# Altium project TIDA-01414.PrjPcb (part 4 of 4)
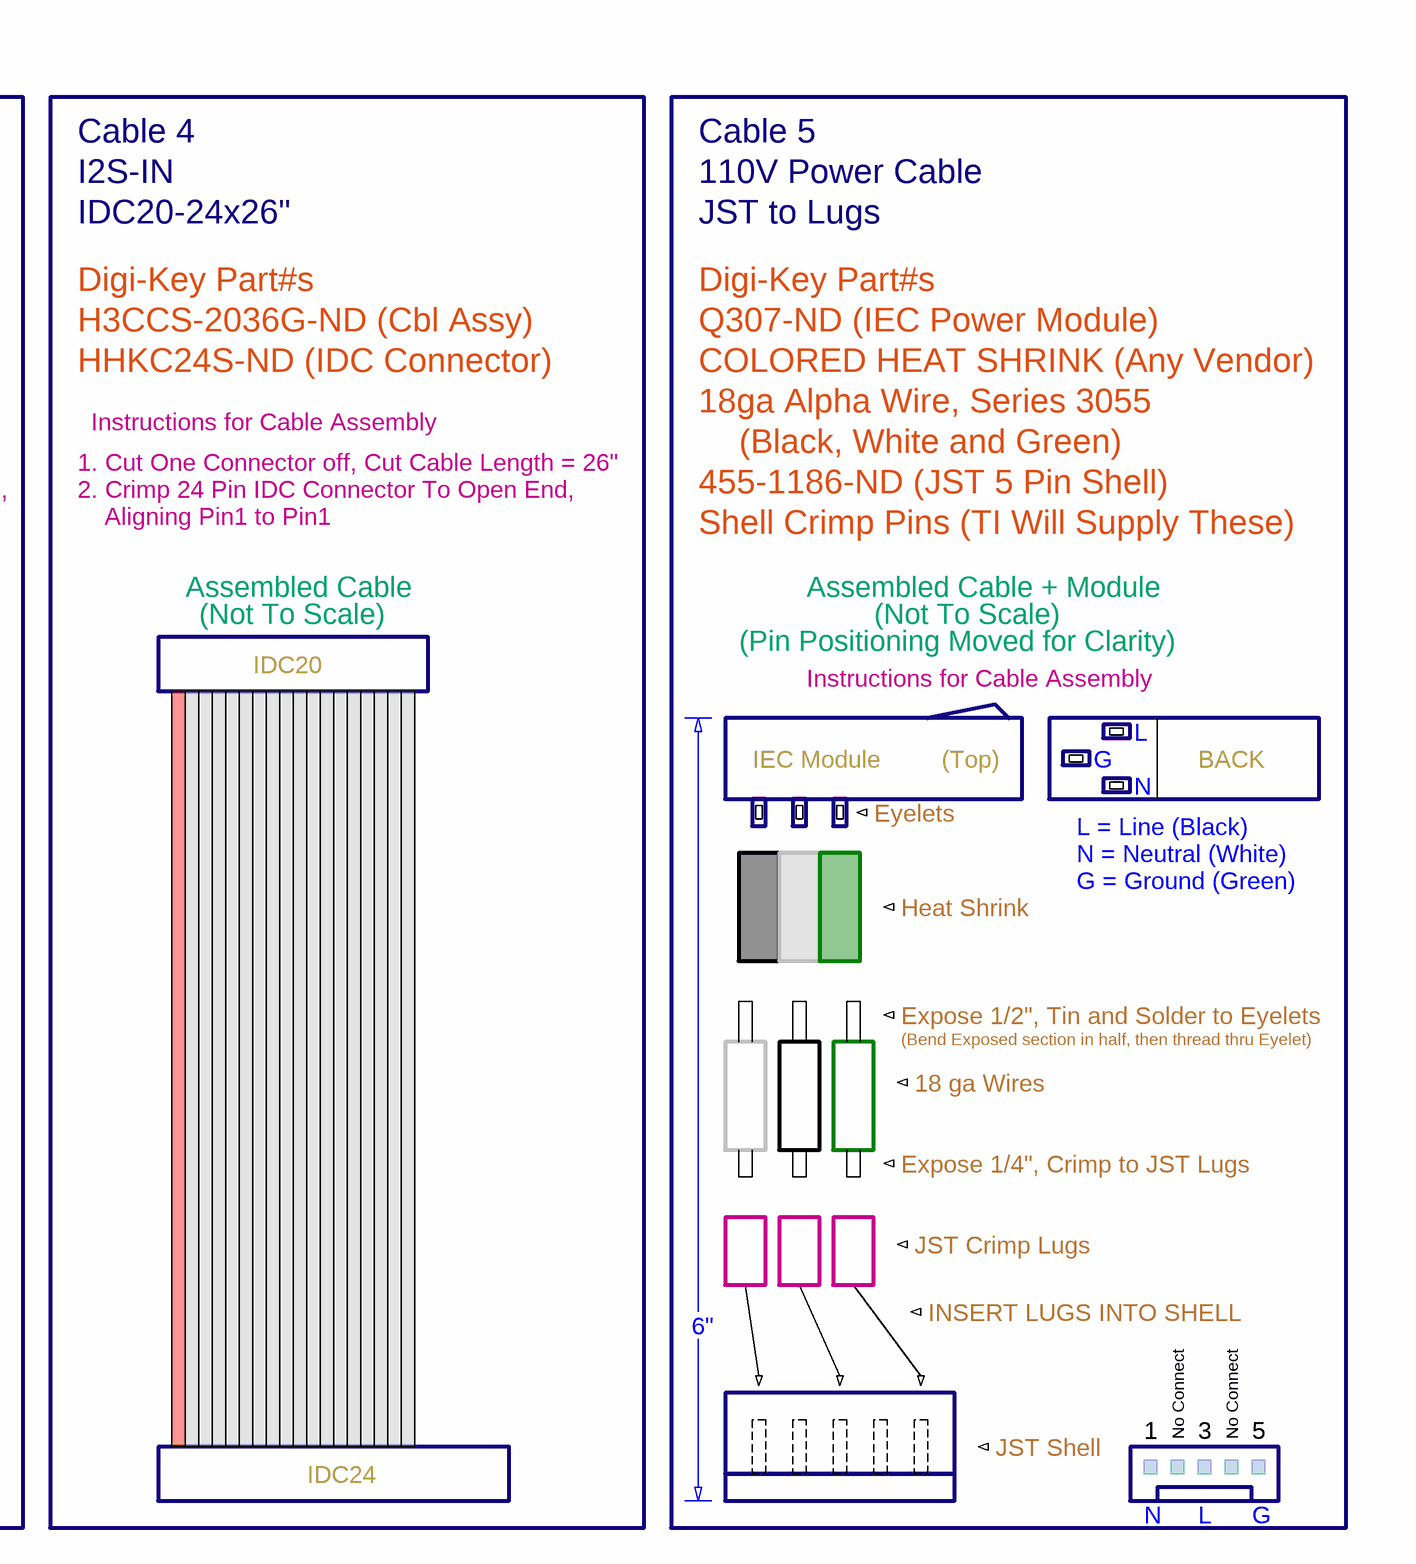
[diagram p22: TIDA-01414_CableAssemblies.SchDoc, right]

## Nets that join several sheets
3.3V: TIDA-01414_Control (30 pins), TIDA-01414_SurroundChannel (J2.6 J2.8), TIDA-01414_SubWooferChannel (11 pins), TIDA-01414_PowerSupplies (J1.1 J8.1)
3.3V-2: TIDA-01414_FrontLeftChannel (11 pins), TIDA-01414_CenterChannel (11 pins), TIDA-01414_PowerSupplies (C24.1 D15.1 VR5.4)
3.3V-3: TIDA-01414_Control (21 pins), TIDA-01414_ClockDrivers (20 pins), TIDA-01414_PowerSupplies (J1.2)
3.3V-4: TIDA-01414_SurroundChannel (15 pins), TIDA-01414_UpChannel (11 pins), TIDA-01414_FrontRightChannel (11 pins), TIDA-01414_PowerSupplies (J6.2)
12V: TIDA-01414_ClockDrivers (R18.1 R26.1), TIDA-01414_SurroundChannel (5 pins), TIDA-01414_UpChannel (5 pins), TIDA-01414_FrontRightChannel (5 pins), TIDA-01414_FrontLeftChannel (5 pins), TIDA-01414_CenterChannel (5 pins), TIDA-01414_SubWooferChannel (L600.1), TIDA-01414_PowerSupplies (J4.1 R49.1)
12V-DC: TIDA-01414_SurroundChannel (J2.2 J2.4), TIDA-01414_PowerSupplies (J5.2)
GND: TIDA-01414_Control (62 pins), TIDA-01414_ClockDrivers (42 pins), TIDA-01414_SurroundChannel (84 pins), TIDA-01414_UpChannel (52 pins), TIDA-01414_FrontRightChannel (52 pins), TIDA-01414_FrontLeftChannel (52 pins), TIDA-01414_CenterChannel (52 pins), TIDA-01414_SubWooferChannel (30 pins), TIDA-01414_PowerSupplies (38 pins)
PVDD: TIDA-01414_SurroundChannel (12 pins), TIDA-01414_UpChannel (12 pins), TIDA-01414_FrontRightChannel (12 pins), TIDA-01414_FrontLeftChannel (12 pins), TIDA-01414_CenterChannel (12 pins), TIDA-01414_PowerSupplies (8 pins)
~{AMP-RESET1}: TIDA-01414_Control (R54.1 U1.2), TIDA-01414_SurroundChannel (U101.5)
~{AMP-RESET2}: TIDA-01414_Control (R55.1 U1.3), TIDA-01414_UpChannel (U201.5)
~{AMP-RESET3}: TIDA-01414_Control (R56.1 U1.4), TIDA-01414_FrontRightChannel (U301.5)
~{AMP-RESET4}: TIDA-01414_Control (R57.1 U1.5), TIDA-01414_FrontLeftChannel (U401.5)
~{AMP-RESET5}: TIDA-01414_Control (R58.1 U1.7), TIDA-01414_CenterChannel (U501.5)
~{CLIP_OTW1}: TIDA-01414_ClockDrivers (R21.2), TIDA-01414_SurroundChannel (U101.2)
~{CLIP_OTW2}: TIDA-01414_ClockDrivers (R22.2), TIDA-01414_UpChannel (U201.2)
~{CLIP_OTW3}: TIDA-01414_ClockDrivers (R23.2), TIDA-01414_FrontRightChannel (U301.2)
~{CLIP_OTW4}: TIDA-01414_ClockDrivers (R24.2), TIDA-01414_FrontLeftChannel (U401.2)
~{CLIP_OTW5}: TIDA-01414_ClockDrivers (R25.2), TIDA-01414_CenterChannel (U501.2)
~{FAULT1}: TIDA-01414_ClockDrivers (R29.2), TIDA-01414_SurroundChannel (U101.4)
~{FAULT2}: TIDA-01414_ClockDrivers (R30.2), TIDA-01414_UpChannel (U201.4)
~{FAULT3}: TIDA-01414_ClockDrivers (R31.2), TIDA-01414_FrontRightChannel (U301.4)
~{FAULT4}: TIDA-01414_ClockDrivers (R32.2), TIDA-01414_FrontLeftChannel (U401.4)
~{FAULT5}: TIDA-01414_ClockDrivers (R33.2), TIDA-01414_CenterChannel (U501.4)
BCK1: TIDA-01414_ClockDrivers (R75.1), TIDA-01414_SurroundChannel (U100.27)
BCK2: TIDA-01414_ClockDrivers (R76.1), TIDA-01414_UpChannel (U200.27)
BCK3: TIDA-01414_ClockDrivers (R77.1), TIDA-01414_FrontRightChannel (U300.27)
BCK4: TIDA-01414_ClockDrivers (R78.1), TIDA-01414_FrontLeftChannel (U400.27)
BCK5: TIDA-01414_ClockDrivers (R79.1), TIDA-01414_CenterChannel (U500.27)
BCK6: TIDA-01414_ClockDrivers (R80.1), TIDA-01414_SubWooferChannel (I2S-OUT.3 U600.27)
DIN0: TIDA-01414_ClockDrivers (U5.4), TIDA-01414_FrontRightChannel (U300.28), TIDA-01414_FrontLeftChannel (U400.28)
DIN1: TIDA-01414_ClockDrivers (U7.4), TIDA-01414_SurroundChannel (U100.28)
DIN2: TIDA-01414_ClockDrivers (U9.4), TIDA-01414_CenterChannel (U500.28), TIDA-01414_SubWooferChannel (DIN2-SEL.2 U600.28)
DIN3: TIDA-01414_ClockDrivers (U10.4), TIDA-01414_UpChannel (U200.28)
INA2: TIDA-01414_SurroundChannel (J2.20), TIDA-01414_UpChannel (JP200.3)
INA3: TIDA-01414_SurroundChannel (J2.28), TIDA-01414_FrontRightChannel (JP300.3)
INA4: TIDA-01414_SurroundChannel (J2.36), TIDA-01414_FrontLeftChannel (JP400.3)
INA5: TIDA-01414_SurroundChannel (J2.44), TIDA-01414_CenterChannel (JP500.3)
INB2: TIDA-01414_SurroundChannel (J2.22), TIDA-01414_UpChannel (JP201.3)
INB3: TIDA-01414_SurroundChannel (J2.30), TIDA-01414_FrontRightChannel (JP301.3)
INB4: TIDA-01414_SurroundChannel (J2.38), TIDA-01414_FrontLeftChannel (JP401.3)
INB5: TIDA-01414_SurroundChannel (J2.46), TIDA-01414_CenterChannel (JP501.3)
INC2: TIDA-01414_SurroundChannel (J2.24), TIDA-01414_UpChannel (JP202.3)
INC3: TIDA-01414_SurroundChannel (J2.32), TIDA-01414_FrontRightChannel (JP302.3)
INC4: TIDA-01414_SurroundChannel (J2.40), TIDA-01414_FrontLeftChannel (JP402.3)
INC5: TIDA-01414_SurroundChannel (J2.48), TIDA-01414_CenterChannel (JP502.3)
IND2: TIDA-01414_SurroundChannel (J2.26), TIDA-01414_UpChannel (JP203.3)
IND3: TIDA-01414_SurroundChannel (J2.34), TIDA-01414_FrontRightChannel (JP303.3)
IND4: TIDA-01414_SurroundChannel (J2.42), TIDA-01414_FrontLeftChannel (JP403.3)
IND5: TIDA-01414_SurroundChannel (J2.50), TIDA-01414_CenterChannel (JP503.3)
LRCK1: TIDA-01414_ClockDrivers (R87.1), TIDA-01414_SurroundChannel (U100.31)
LRCK2: TIDA-01414_ClockDrivers (R88.1), TIDA-01414_UpChannel (U200.31)
LRCK3: TIDA-01414_ClockDrivers (R89.1), TIDA-01414_FrontRightChannel (U300.31)
LRCK4: TIDA-01414_ClockDrivers (R90.1), TIDA-01414_FrontLeftChannel (U400.31)
LRCK5: TIDA-01414_ClockDrivers (R91.1), TIDA-01414_CenterChannel (U500.31)
LRCK6: TIDA-01414_ClockDrivers (R92.1), TIDA-01414_SubWooferChannel (I2S-OUT.7 U600.31)
OSC-IOM: TIDA-01414_SurroundChannel (U102.4), TIDA-01414_UpChannel (U201.14), TIDA-01414_FrontRightChannel (U301.14), TIDA-01414_FrontLeftChannel (U401.14), TIDA-01414_CenterChannel (U501.14)
OSC-IOP: TIDA-01414_SurroundChannel (U103.4), TIDA-01414_UpChannel (U201.13), TIDA-01414_FrontRightChannel (U301.13), TIDA-01414_FrontLeftChannel (U401.13), TIDA-01414_CenterChannel (U501.13)
SCK1: TIDA-01414_ClockDrivers (R81.1), TIDA-01414_SurroundChannel (U100.26)
SCK2: TIDA-01414_ClockDrivers (R82.1), TIDA-01414_UpChannel (U200.26)
SCK3: TIDA-01414_ClockDrivers (R83.1), TIDA-01414_FrontRightChannel (U300.26)
SCK4: TIDA-01414_ClockDrivers (R84.1), TIDA-01414_FrontLeftChannel (U400.26)
SCK5: TIDA-01414_ClockDrivers (R85.1), TIDA-01414_CenterChannel (U500.26)
SCK6: TIDA-01414_ClockDrivers (R86.1), TIDA-01414_SubWooferChannel (I2S-OUT.17 U600.26)
SCL1: TIDA-01414_Control (R15.1 U3.2), TIDA-01414_SurroundChannel (U100.18)
SCL2: TIDA-01414_Control (R11.1 U3.4), TIDA-01414_UpChannel (U200.18)
SCL3: TIDA-01414_Control (R9.1 U3.6), TIDA-01414_FrontRightChannel (U300.18)
SCL4: TIDA-01414_Control (R7.1 U3.8), TIDA-01414_FrontLeftChannel (U400.18)
SCL5: TIDA-01414_Control (R5.1 U3.11), TIDA-01414_CenterChannel (U500.18)
SCL6: TIDA-01414_Control (R3.1 U3.13), TIDA-01414_SubWooferChannel (I2S-OUT.16 J601.1)
SDA1: TIDA-01414_Control (R16.1 U3.1), TIDA-01414_SurroundChannel (U100.17)
SDA2: TIDA-01414_Control (R14.1 U3.3), TIDA-01414_UpChannel (U200.17)
SDA3: TIDA-01414_Control (R10.1 U3.5), TIDA-01414_FrontRightChannel (U300.17)
SDA4: TIDA-01414_Control (R8.1 U3.7), TIDA-01414_FrontLeftChannel (U400.17)
SDA5: TIDA-01414_Control (R6.1 U3.10), TIDA-01414_CenterChannel (U500.17)
SDA6: TIDA-01414_Control (R4.1 U3.12), TIDA-01414_SubWooferChannel (I2S-OUT.20 J600.1)

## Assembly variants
001: not fitted FID1 FID2 FID3 FID4 FID5 FID6 GND-IN PWR-IN R35 R47 R94 R110 R111 R210 R211 R310 R311 R410 R411 R510 R511 R612 R613 TP2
